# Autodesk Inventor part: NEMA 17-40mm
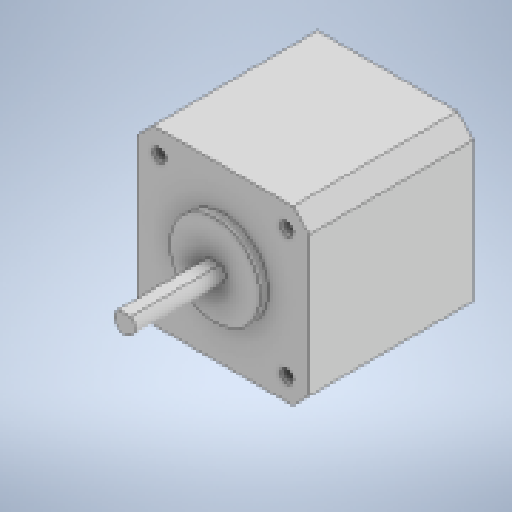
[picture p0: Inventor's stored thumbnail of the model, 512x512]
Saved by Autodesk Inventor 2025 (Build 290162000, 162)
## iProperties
Created: 2026-03
Part Number: NEMA 17-40mm
Material: Generico
Description: NEMA 17
Document SubType Name: Modeling
Designer: R5800u
Density: 1 g/cm^3
Appearance: Default
Author: R5800u
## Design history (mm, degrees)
node "NEMA 17"
sketch "Schizzo1"
  geometry: L1 (-2.707, 42)-(39.293, 42); L2 (39.293, 42)-(39.293, 0); L3 (39.293, 0)-(-2.707, 0); L4 (-2.707, 0)-(-2.707, 42); L5 (-2.707, 42)-(39.293, 0); L6 (39.293, 42)-(-2.707, 0); L7 (50.204, 58.756)-(-13.618, 58.756); L8 (-13.618, 58.756)-(-13.618, -16.756); L9 (-13.618, -16.756)-(50.204, -16.756); L10 (50.204, -16.756)-(50.204, 58.756); L11 (50.204, 58.756)-(-13.618, -16.756); L12 (-13.618, 58.756)-(50.204, -16.756); A1 r 2.5 centre (18.293, 21) between (16.793, 23) and (19.793, 23) reference; 1 further point
  constraints: 24 end point, 4 midpoint, 4 parallel, 2 horizontal, 2 perpendicular
  dimensions: "d0" = 42 distance of L2.end L3.end; "d1" = 42 distance of L1.end L2.end
extrude "Estrusione1" cut sketch "Schizzo1" extent not by distance; stored distance "d2" = 0; taper "d3" = 0 deg
sketch "Schizzo2"
  geometry: L1 (1.5, 2)-(-1.5, 2) reference; A1 r 2.5 centre (0, 0) between (-1.5, 2) and (1.5, 2) reference; 1 further point
extrude "Estrusione2" cut sketch "Schizzo2" distance "d4" = 1; taper "d5" = 0 deg
chamfer "Smusso1" distance "d6" = 4; stored, may be unused: second distance "d7" = 2, angle "d8" = 45 deg
sketch "Schizzo3"
  geometry: L1 (38, -38)-(34, -42) reference; L2 (38, -38)-(38, -4) reference; L3 (34, 0)-(38, -4) reference; L4 (34, 0)-(0, 0) reference; L5 (-4, -4)-(0, 0) reference; L6 (-4, -4)-(-4, -38) reference; L7 (0, -42)-(-4, -38) reference; L8 (0, -42)-(34, -42) reference; C1 r 1.6 at (1.5, -5.5) reference; C2 r 1.6 at (1.5, -36.5) reference; C3 r 1.6 at (32.5, -36.5) reference; C4 r 1.6 at (32.5, -5.5) reference; 1 further point
extrude "Estrusione3" join sketch "Schizzo3" distance "d9" = 2; taper "d10" = 0 deg
sketch "Schizzo4"
  geometry: L1 (11, -46)-(23, -46); L2 (23, -46)-(23, -34); L3 (23, -34)-(11, -34); L4 (11, -34)-(11, -46); L5 (34, -40)-(0, -40) reference; L6 (11, -46)-(23, -34); L7 (23, -46)-(11, -34); 4 further points
  constraints: 12 end point, 3 midpoint, 2 parallel, 1 horizontal, 1 perpendicular
  dimensions: "d11" = 12 distance of L3.end L2.end; "d12" = 12 distance of L2.end L1.end
extrude "Estrusione4" join sketch "Schizzo4" distance "d13" = 4; taper "d14" = 0 deg
node "Solido1"
node "Linea chiusa proiettata1"
node "Linea chiusa proiettata2"
